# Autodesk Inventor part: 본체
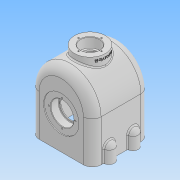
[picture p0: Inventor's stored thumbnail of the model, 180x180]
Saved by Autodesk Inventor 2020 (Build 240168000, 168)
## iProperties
Created: 2023-03
Part Number: 본체
Material: 일반
Document SubType Name: Modeling
Designer: user
Density: 1 g/cm^3
Appearance: 기본값
Mass: 844.028 g
Surface Area: 1798.4 cm^2
Volume: 844.028 cm^3
Author: user
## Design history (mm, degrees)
sketch "스케치1"
  geometry: L1 (70, 94)-(70, 0); L2 (70, 0)-(-70, 0); L3 (-70, 0)-(-70, 94); A1 r 70 centre (0, 94) between (70, 94) and (-70, 94); 2 further points
  constraints: 6 end point, 2 point on circle, 1 centre point, 1 coincident, 1 midpoint, 1 parallel
  dimensions: "d0" = 140 diameter of A1; "d1" = 94 distance of point (0, 0) A1.centre
extrude "돌출1" new body sketch "스케치1" stored distance "d2" = 130; taper "d3" = 0 deg
fillet "모깎기1" dims "d4" = 20
feature "쉘1" dims "d5" = 10
sketch "스케치2"
  geometry: L1 (144, -65)-(0, -65) reference; L2 (0, -65)-(0, -55) reference; L3 (0, -55)-(144, -55) reference; L4 (154, -45)-(154, 45) reference; L5 (144, 55)-(0, 55) reference; L6 (0, 55)-(0, 65) reference; L7 (0, 65)-(144, 65) reference; L8 (164, 45)-(164, -45) reference; L9 (75, -43)-(75, -65); L10 (98, -65)-(117, -65); L11 (117, -65)-(117, -55); L12 (144, -55)-(94, -55) reference; L13 (117, -55)-(105, -43); L14 (105, -43)-(98, -43); L15 (94, -45)-(94, 45) reference; L16 (98, -43)-(98, -65); L17 (94, -65)-(0, -65) reference; L18 (85.853, 0)-(62, 0); A1 r 20 centre (144, -45) between (144, -65) and (164, -45) reference; A2 r 10 centre (144, -45) between (144, -55) and (154, -45) reference; A3 r 10 centre (144, 45) between (154, 45) and (144, 55) reference; A4 r 20 centre (144, 45) between (164, 45) and (144, 65) reference; 1 further point
  constraints: 14 end point, 4 point on line, 3 perpendicular, 1 horizontal, 1 horizontal alignment, 1 vertical
  dimensions: "d6" = 60 diameter of L13.end L9; "d7" = 135 deg angle of L12 L13; "d8" = 22 distance of L14.end L10.start; "d9" = 75 horizontal distance of L2.end L9.end; "d10" = 46 diameter of L16 L9
revolve "회전1" sketch "스케치2" stored, may be unused: angle "d11" = 90 deg
sketch "스케치3"
  geometry: L1 (-50, 0)-(50, 0) reference; 3 further points
  constraints: 1 midpoint, 1 vertical alignment
  dimensions: "d12" = 75 distance of point (0, 0) point (0, 75)
hole "구멍1" sketch "스케치3" at (0, 75) diameter "d13" = 46; stored, may be unused: countersink angle "d17" = 90 deg, drill point angle "d19" = 118 deg; dims "d14" = 6, "d15" = 52, "d16" = 20, "d18" = 30
sketch "스케치4"
  geometry: C1 r 26 at (0, 75) reference; 1 further point
hole "구멍2" sketch "스케치4" at (0, 75) diameter "d20" = 80; stored, may be unused: countersink angle "d24" = 90 deg, drill point angle "d26" = 0 deg; dims "d21" = 6, "d22" = 52, "d23" = 20, "d25" = 2
sketch "스케치5"
  geometry: C1 r 40 at (0, 0) reference; C2 r 26 at (0, 0) reference; C3 r 30 at (0, 0); 6 further points
  constraints: 2 vertical alignment, 1 centre point, 1 coincident, 6 other
  dimensions: "d27" = 60 diameter of C3; "d30" = 360 deg dimension on C3.centre point (0, 30) (derived)
hole "구멍3" sketch "스케치5" at (0, 30), (30, 0), (0, -30), (-30, 0) diameter "d32" = 3.242; stored, may be unused: countersink angle "d36" = 90 deg, drill point angle "d38" = 118 deg; dims "d33" = 8, "d34" = 52, "d35" = 20, "d37" = 10
node "작업 평면1"
sketch "스케치6"
  geometry: C1 r 35 at (50, -65); 1 further point
  constraints: 1 centre point, 1 coincident
  dimensions: "d40" = 70 diameter of C1
extrude "돌출2" join sketch "스케치6" stored distance "d41" = 130; taper "d42" = 0 deg
sketch "스케치7"
  geometry: C1 r 35 at (0, 0) reference; 2 further points
  constraints: 1 coincident
hole "구멍4" sketch "스케치7" at (0, 0) diameter "d43" = 34; stored, may be unused: countersink angle "d47" = 90 deg, drill point angle "d49" = 118 deg; dims "d44" = 8, "d45" = 43, "d46" = 22, "d48" = 10
sketch "스케치8" dims "d50" = 52
  geometry: C1 r 21.5 at (0, 0) reference; C2 r 35 at (0, 0) reference; 5 further points
  constraints: 2 vertical alignment, 1 coincident, 7 other
  dimensions: "d53" = 360 deg dimension on point (0, 0) point (0, 26) (derived)
hole "구멍5" sketch "스케치8" at (0, 26), (-26, 0), (0, -26), (26, 0) diameter "d55" = 3.242; stored, may be unused: countersink angle "d59" = 90 deg, drill point angle "d61" = 118 deg; dims "d56" = 8, "d57" = 43, "d58" = 22, "d60" = 10
sketch "스케치9"
  geometry: L1 (110, -20)-(110, -110) reference; L2 (-10, -110)-(-10, -20) reference; L3 (120, -20)-(120, -110) reference; L4 (-20, -110)-(-20, -20) reference; L5 (-10, -31.367)-(-10, -44.633); L6 (-10, -85.367)-(-10, -98.633); L7 (110, -85.367)-(110, -98.633); L8 (110, -31.367)-(110, -44.633); L9 (110, -110)-(110, -20) reference; A1 r 12 centre (-20, -38) between (-10, -31.367) and (-10, -44.633); A2 r 12 centre (-20, -92) between (-10, -85.367) and (-10, -98.633); A3 r 12 centre (120, -38) between (110, -44.633) and (110, -31.367); A4 r 12 centre (120, -92) between (110, -98.633) and (110, -85.367); 2 further points
  constraints: 13 point on line, 8 end point, 8 point on circle, 4 centre point, 2 collinear, 2 horizontal alignment, 1 parallel
  dimensions: "d62" = 24 diameter of A1; "d63" = 24 diameter of A2; "d64" = 24 diameter of A3; "d65" = 24 diameter of A4; "d66" = 54 distance of A4.centre A3.centre; "d67" = 27 vertical distance of point (50, -65) A3.centre
extrude "돌출3" join sketch "스케치9" distance "d68" = 28; taper "d69" = 0 deg
sketch "스케치12"
  geometry: L1 (120, 50)-(120, 26) reference; L2 (120, 80)-(120, 50) reference; L3 (120, 110)-(120, 104) reference; L4 (0, 130)-(100, 130) reference; L5 (-20, 104)-(-20, 110) reference; L6 (-20, 80)-(-20, 104) reference; L7 (120, 26)-(120, 20) reference; L8 (100, 0)-(0, 0) reference; L9 (-20, 20)-(-20, 26) reference; L10 (-20, 26)-(-20, 50) reference; L11 (120, 104)-(120, 80) reference; L12 (-20, 50)-(-20, 80) reference; L13 (100, 120)-(0, 120) reference; L14 (-10, 110)-(-10, 20) reference; L15 (0, 10)-(100, 10) reference; L16 (110, 20)-(110, 110) reference; L17 (120, 38)-(132, 38); L18 (120, 50)-(120, 80) reference; L19 (120, 50)-(120, 38); A1 r 12 centre (120, 38) between (120, 26) and (120, 50) reference; A2 r 12 centre (120, 92) between (120, 80) and (120, 104) reference; A3 r 20 centre (100, 110) between (120, 110) and (100, 130) reference; A4 r 20 centre (0, 110) between (0, 130) and (-20, 110) reference; A5 r 12 centre (-20, 92) between (-20, 104) and (-20, 80) reference; A6 r 20 centre (100, 20) between (100, 0) and (120, 20) reference; A7 r 20 centre (0, 20) between (-20, 20) and (0, 0) reference; A8 r 12 centre (-20, 38) between (-20, 50) and (-20, 26) reference; A9 r 10 centre (0, 110) between (0, 120) and (-10, 110) reference; A10 r 10 centre (0, 20) between (-10, 20) and (0, 10) reference; A11 r 10 centre (100, 20) between (100, 10) and (110, 20) reference; A12 r 10 centre (100, 110) between (110, 110) and (100, 120) reference; A13 r 12 centre (120, 38) between (120, 26) and (120, 50); A14 r 12 centre (120, 38) between (120, 26) and (120, 50) reference; 2 further points
  constraints: 4 end point, 4 point on circle, 2 point on line, 1 centre point, 1 coincident
  dimensions: "d71" = 24 diameter of A13
revolve "회전2" sketch "스케치12" stored, may be unused: angle "d72" = 90 deg
sketch "스케치13"
  geometry: A1 r 12 centre (120, 38) between (120, 26) and (120, 50) reference; A2 r 12 centre (120, 92) between (120, 80) and (120, 104) reference; A3 r 12 centre (-20, 92) between (-20, 104) and (-20, 80) reference; A4 r 12 centre (-20, 38) between (-20, 50) and (-20, 26) reference; 1 further point
hole "구멍6" sketch "스케치13" at (120, 92), (120, 38), (-20, 38), (-20, 92) diameter "d73" = 10.106; stored, may be unused: countersink angle "d77" = 90 deg, drill point angle "d79" = 118 deg; dims "d74" = 24, "d75" = 43, "d76" = 22, "d78" = 26
node "작업 평면2"
sketch "스케치14"
  geometry: L1 (-1.449, 25.069)-(-1.449, -25.069); L2 (-1.449, -25.069)-(-14.551, -25.069); L3 (-14.551, -25.069)-(-14.551, 25.069); L4 (-14.551, 25.069)-(-1.449, 25.069); L5 (-8, 25.069)-(-8, -25.069); L6 (-1.449, 0)-(-14.551, 0); L7 (-178, 15)-(-178, -15) reference; L8 (0, 35)-(0, -35) reference; 2 further points
  constraints: 5 midpoint, 4 end point, 1 horizontal alignment, 1 vertical, 2 other
  dimensions: "d80" = 8 distance between parallel lines of L5 L8
feature "엠보싱1" sketch "스케치14" dims "d0" = 140, "d1" = 94, "d81" = 0.5, "d82" = 0
chamfer "모따기1" distance "d83" = 1; stored, may be unused: second distance "d84" = 2, angle "d85" = 45 deg
fillet "모깎기2" dims "d86" = 1
fillet "모깎기3" dims "d87" = 3
fillet "모깎기4" dims "d88" = 3
node "솔리드1"
mirror "미러1"
mirror "미러2"
mirror "미러3"
mirror "미러4"
node "절단 모서리 투영1"
node "절단 모서리 투영3"
feature "A9D066F2-1C7D-4E18-AEED-F7BC21143FA4" dims "d13" = 46, "d14" = 6, "d15" = 52, "d16" = 20, "d17" = 90 deg, "d18" = 30, "d19" = 118 deg
other parameters: "d39" = -178
